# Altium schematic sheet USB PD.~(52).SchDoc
size A3; SheetNumber: 5; SheetTotal: 7
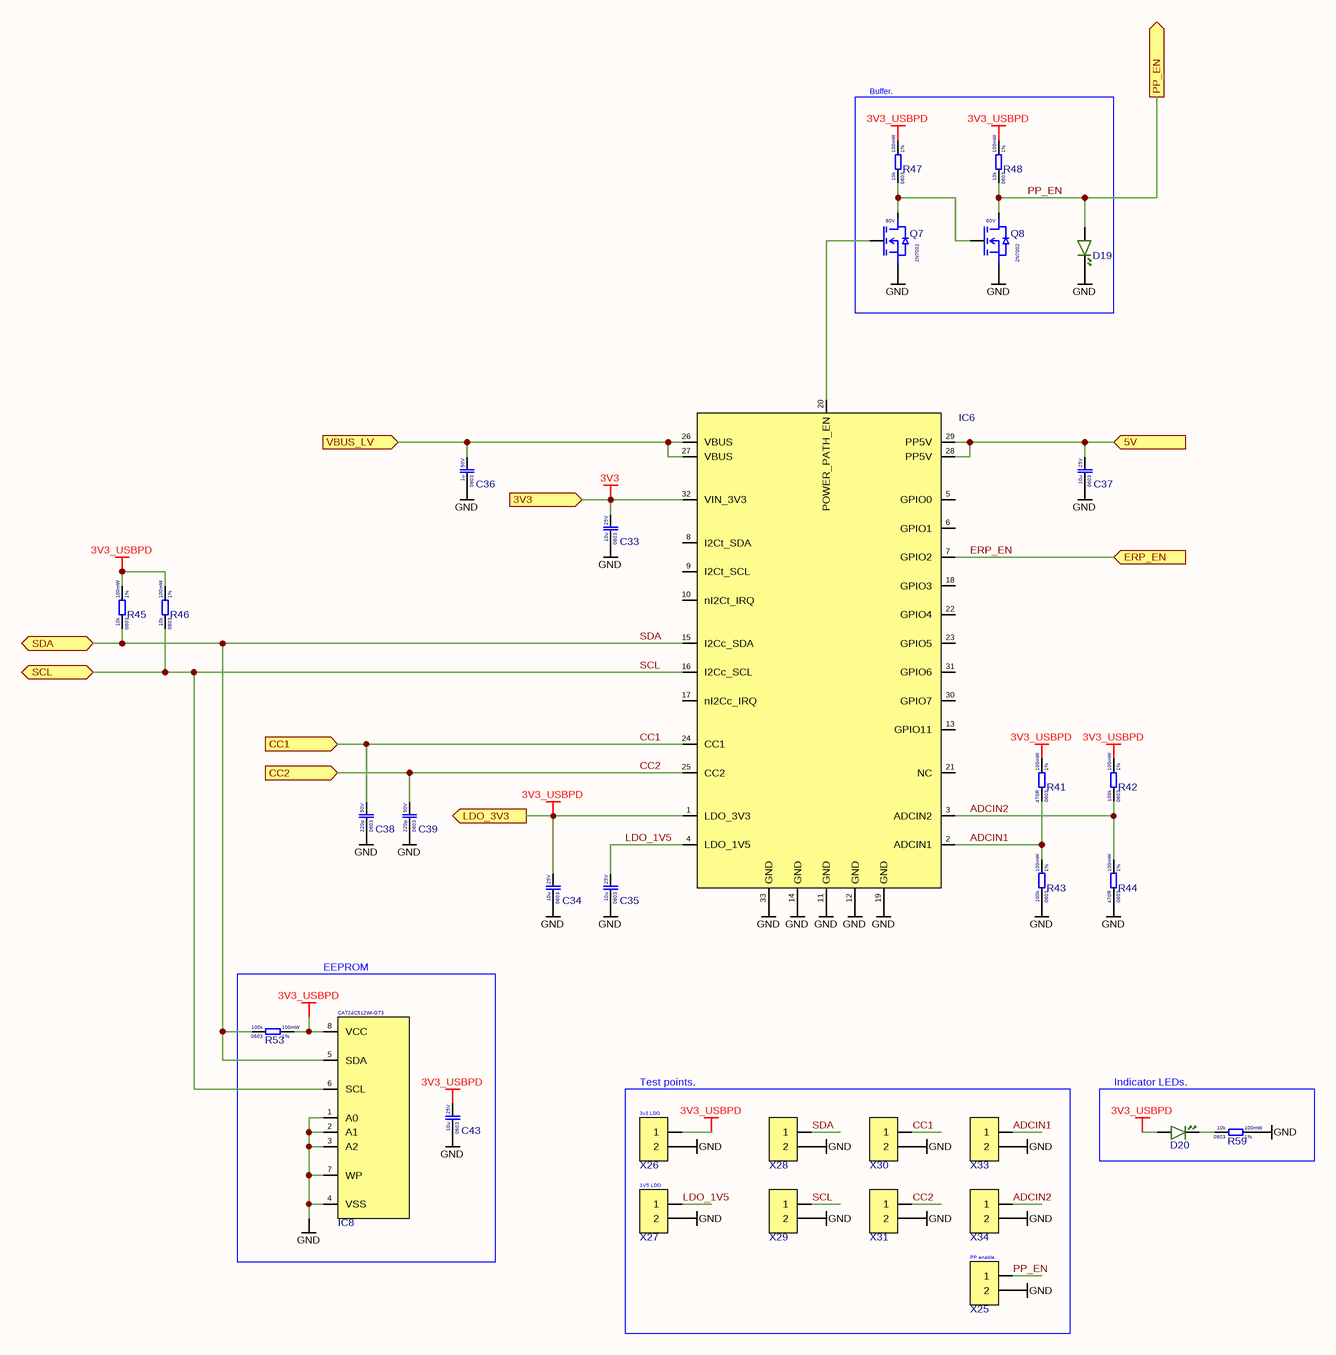
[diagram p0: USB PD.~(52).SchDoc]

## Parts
C33  Voltage Rating: 25V  Case Code (Imperial): 0603  Capacitance: 10u  [CAP 0603]  (hidden comment: CL10A106MA8NRNC)
C34  Voltage Rating: 25V  Case Code (Imperial): 0603  Capacitance: 10u  [CAP 0603]  (hidden comment: CL10A106MA8NRNC)
C35  Voltage Rating: 25V  Case Code (Imperial): 0603  Capacitance: 10u  [CAP 0603]  (hidden comment: CL10A106MA8NRNC)
C36  Voltage Rating: 50V  Case Code (Imperial): 0603  Capacitance: 1u  [CAP 0603]  (hidden comment: CL10A105KB8NNNC)
C37  Voltage Rating: 25V  Case Code (Imperial): 0603  Capacitance: 10u  [CAP 0603]  (hidden comment: CL10A106MA8NRNC)
C38  Voltage Rating: 50V  Case Code (Imperial): 0603  Capacitance: 220p  [CAP 0603]  (hidden comment: CL10B221KB8NNNC)
C39  Voltage Rating: 50V  Case Code (Imperial): 0603  Capacitance: 220p  [CAP 0603]  (hidden comment: CL10B221KB8NNNC)
C43  Voltage Rating: 25V  Case Code (Imperial): 0603  Capacitance: 10u  [CAP 0603]  (hidden comment: CL10A106MA8NRNC)
D19  PSC-1608U52GC-G4  [DIODE_0603]  (value not drawn)
D20  Diode LED Green  [DIODE_0603]  (value not drawn)
IC6  TPS26750SRSMR  [VQFN (32) 4x4]  (value not drawn)
IC8  CAT24C512WI-GT3  [SOIC8]
Q7  Voltage: 60V  [SOT-23 GSD]  (hidden comment: 2N7002)
Q8  Voltage: 60V  [SOT-23 GSD]  (hidden comment: 2N7002)
R41  Resistance Tolerance: 1%  Resistance: 470R  Power Rating: 100mW  Case Code (Imperial): 0603  [RES_0603]  (hidden comment: 0603WAF4700T5E)
R42  Resistance Tolerance: 1%  Resistance: 100k  Power Rating: 100mW  Case Code (Imperial): 0603  [RES_0603]  (hidden comment: 0603WAF1003T5E)
R43  Resistance Tolerance: 1%  Resistance: 100k  Power Rating: 100mW  Case Code (Imperial): 0603  [RES_0603]  (hidden comment: 0603WAF1003T5E)
R44  Resistance Tolerance: 1%  Resistance: 470R  Power Rating: 100mW  Case Code (Imperial): 0603  [RES_0603]  (hidden comment: 0603WAF4700T5E)
R45  Resistance Tolerance: 1%  Resistance: 10k  Power Rating: 100mW  Case Code (Imperial): 0603  [RES_0603]  (hidden comment: 0603WAF1002T5E)
R46  Resistance Tolerance: 1%  Resistance: 10k  Power Rating: 100mW  Case Code (Imperial): 0603  [RES_0603]  (hidden comment: 0603WAF1002T5E)
R47  Resistance Tolerance: 1%  Resistance: 10k  Power Rating: 100mW  Case Code (Imperial): 0603  [RES_0603]  (hidden comment: 0603WAF1002T5E)
R48  Resistance Tolerance: 1%  Resistance: 10k  Power Rating: 100mW  Case Code (Imperial): 0603  [RES_0603]  (hidden comment: 0603WAF1002T5E)
R53  Resistance Tolerance: 1%  Resistance: 100k  Power Rating: 100mW  Case Code (Imperial): 0603  [RES_0603]  (hidden comment: 0603WAF1003T5E)
R59  Resistance Tolerance: 1%  Resistance: 10k  Power Rating: 100mW  Case Code (Imperial): 0603  [RES_0603]  (hidden comment: 0603WAF1002T5E)
X25  ZX-PZ1.27-1-2PZZ  [Pin header 1x2 1.27mmP THT Vertical]  (value not drawn)
X26  ZX-PZ1.27-1-2PZZ  [Pin header 1x2 1.27mmP THT Vertical]  (value not drawn)
X27  ZX-PZ1.27-1-2PZZ  [Pin header 1x2 1.27mmP THT Vertical]  (value not drawn)
X28  ZX-PZ1.27-1-2PZZ  [Pin header 1x2 1.27mmP THT Vertical]  (value not drawn)
X29  ZX-PZ1.27-1-2PZZ  [Pin header 1x2 1.27mmP THT Vertical]  (value not drawn)
X30  ZX-PZ1.27-1-2PZZ  [Pin header 1x2 1.27mmP THT Vertical]  (value not drawn)
X31  ZX-PZ1.27-1-2PZZ  [Pin header 1x2 1.27mmP THT Vertical]  (value not drawn)
X33  ZX-PZ1.27-1-2PZZ  [Pin header 1x2 1.27mmP THT Vertical]  (value not drawn)
X34  ZX-PZ1.27-1-2PZZ  [Pin header 1x2 1.27mmP THT Vertical]  (value not drawn)

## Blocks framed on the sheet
Buffer.: D19 Q7 Q8 R47 R48
EEPROM: C43 IC8 R53
Test points.: X25-X31 X33 X34
Indicator LEDs.: D20 R59

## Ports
3V3 (in, see Arhitecture[4B], Power distribution[5D]), 5V (in, see Arhitecture[4B], Power distribution[5C]), CC1 (in, see Arhitecture[3B], USB protection[5B]), CC2 (in, see Arhitecture[3B], USB protection[5B]), ERP_EN (in, see Arhitecture[3B], USB protection[5C]), LDO_3V3 (out, see Arhitecture[3B], USB protection[5B]), PP_EN (out, see Arhitecture[4B], Power path switch[3C]), SCL (bidir, see Arhitecture[4B], Charger[3C]), SDA (bidir, see Arhitecture[4B], Charger[3C]), VBUS_LV (in, see Arhitecture[3B], USB protection[5B])

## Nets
3V3: C33.2 IC6.32(VIN_3V3) ; port 3V3
3V3_USBPD: C34.2 C43.2 D20.A IC6.1(LDO_3V3) IC8.8(VCC) R41.2 R42.2 R45.2 R46.2 R47.2 R48.2 R53.2 X26.1 ; port LDO_3V3
GND: C33.1 C34.1 C35.1 C36.1 C37.1 C38.1 C39.1 C43.1 D19.K IC6.11(GND) IC6.12(GND) IC6.14(GND) IC6.19(GND) IC6.33(GND) IC8.1(A0) IC8.2(A1) IC8.3(A2) IC8.4(VSS) IC8.7(WP) Q7.S Q8.S R43.1 R44.1 R59.2 X25.2 X26.2 X27.2 X28.2 X29.2 X30.2 X31.2 X33.2 X34.2
5V: C37.2 IC6.28(PP5V) IC6.29(PP5V) ; port 5V
ADCIN1: IC6.2(ADCIN1) R41.1 R43.2 X33.1
ADCIN2: IC6.3(ADCIN2) R42.1 R44.2 X34.1
CC1: C38.2 IC6.24(CC1) X30.1 ; port CC1
CC2: C39.2 IC6.25(CC2) X31.1 ; port CC2
ERP_EN: IC6.7(GPIO2) ; port ERP_EN
LDO_1V5: C35.2 IC6.4(LDO_1V5) X27.1
PP_EN: D19.A Q8.D R48.1 X25.1 ; port PP_EN
SCL: IC6.16(I2Cc_SCL) IC8.6(SCL) R46.1 X29.1 ; port SCL
SDA: IC6.15(I2Cc_SDA) IC8.5(SDA) R45.1 R53.1 X28.1 ; port SDA
VBUS_LV: C36.2 IC6.26(VBUS) IC6.27(VBUS) ; port VBUS_LV
NetD20_K: D20.K R59.1
NetIC6_20: IC6.20(POWER_PATH_EN) Q7.G
NetQ7_D: Q7.D Q8.G R47.1

Not connected (* = marked no-connect by the designer): IC6 5(GPIO0) 6(GPIO1) 8(I2Ct_SDA) 9(I2Ct_SCL) 10(nI2Ct_IRQ) 13(GPIO11) 17(nI2Cc_IRQ) 18(GPIO3) 21(NC) 22(GPIO4) 23(GPIO5) 30(GPIO7) 31(GPIO6)

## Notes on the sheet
- (near X26) 3v3 LDO
- (near X27) 1V5 LDO
- (near X25) PP enable.

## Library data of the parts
C33-C35 C37 C43 = CL10A106MA8NRNC: Cap 10uF 25V 0603 X5R; Manufacturer: Samsung
C36 = CL10A105KB8NNNC: Cap 1uF 50V 0603 X5R; Manufacturer: Samsung
C38 C39 = CL10B221KB8NNNC: Cap 220pF 50V 0603 X7R; Manufacturer: Samsung
D19 = PSC-1608U52GC-G4: LED Green 0603 20mA; Manufacturer: HONGLITRONIC
D20 = Diode LED Green: Generic green LED symbol
IC6 = TPS26750SRSMR: USB PD IC EPR 240W; Manufacturer: Texas Instruments
IC8 = CAT24C512WI-GT3: EEPROM SOIC-8; Manufacturer: OnSemi
Q7 Q8 = 2N7002: nMOS 60V 115mA SOT-23; Manufacturer: Jiangsu Changjing Electronics Technology Co., Ltd.
R41 R44 = 0603WAF4700T5E: Res 470R 0603 1% 100mW 75V; Manufacturer: Uni-Royal
R42 R43 R53 = 0603WAF1003T5E: Res 100k 0603 1% 100mW 75V; Manufacturer: Uni-Royal
R45-R48 R59 = 0603WAF1002T5E: Res 10k 0603 1% 100mW 75V; Manufacturer: Uni-Royal
X25-X31 X33 X34 = ZX-PZ1.27-1-2PZZ: Pin header 1x2 1.27mmP THT Vertical; Manufacturer: Megastar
